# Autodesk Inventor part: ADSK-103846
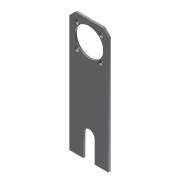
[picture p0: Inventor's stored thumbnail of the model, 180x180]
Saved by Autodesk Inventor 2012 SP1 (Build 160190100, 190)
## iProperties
Shininess: 20.0
Created: 2001-05
Part Number: ADSK-103846
Document SubType Name: Modeling
Designer: Administrator
Stock Number: ADSK-103846
Density: 1 g/cm^3
Material: Default
Density: 0.0
Volumn: 0.0
Area: 0.0
PropertySet Name: Model Information
Control State: 0
Master: False
Checked Out: False
Author: Administrator
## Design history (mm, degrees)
sketch "Sketch1"
  geometry: L1 (-24.57, 245.796)-(64.33, 245.796); L2 (64.33, 245.796)-(64.33, -33.604); L3 (64.33, -33.604)-(-24.57, -33.604); L4 (-24.57, -33.604)-(-24.57, 245.796)
  constraints: 8 end point, 2 parallel, 1 horizontal, 1 perpendicular
  dimensions: "d0" = 279.4 distance of L3.end L1.start; "d1" = 88.9 distance of L2.end L3.end
extrude "Extrusion1" new body sketch "Sketch1" distance "d2" = 4.7752; taper "d3" = 0 deg
sketch "Sketch2"
  geometry: L1 (-24.57, 245.796)-(64.33, 245.796) reference; L2 (-24.57, -33.604)-(-24.57, 245.796) reference; C1 r 32.385 at (19.88, 201.346)
  constraints: 1 centre point
  dimensions: "d4" = 64.77 diameter of C1; "d5" = 44.45 distance from line of L1 C1.centre; "d6" = 44.45 distance from line of L2 C1.centre (= d5)
extrude "Extrusion2" cut sketch "Sketch2" distance "d7" = 6.35; taper "d8" = 0 deg
sketch "Sketch3"
  geometry: L1 (64.33, 245.796)-(64.33, -33.604) reference; L2 (19.88, 201.346)-(46.821, 174.405); C1 r 32.385 at (19.88, 201.346) reference
  constraints: 2 end point
  dimensions: "d21" = 38.1 distance of L2.start L2.end; "d22" = 45 deg angle of L1 L2
hole "Hole1" sketch "Sketch3" at (46.821, 174.405) diameter "d9" = 5.55625; stored, may be unused: countersink angle "d13" = 82 deg, drill point angle "d15" = 118 deg; dims "d10" = 12.7, "d11" = 10.4775, "d12" = 6.35, "d14" = 19.05
pattern_circular "Circular Pattern1" dims angle "d18" = 360 deg
chamfer "Chamfer1" distance "d19" = 12.7; stored, may be unused: second distance "d20" = 12.7, angle "d29" = 45 deg
sketch "Sketch4"
  geometry: L1 (-24.57, -33.604)-(-24.57, 233.096) reference; L2 (64.33, -33.604)-(-24.57, -33.604) reference; L3 (64.33, 233.096)-(64.33, -33.604) reference; L4 (7.18, -33.604)-(32.58, -33.604); L5 (32.58, -33.604)-(32.58, 17.196); L6 (32.58, 17.196)-(7.18, 17.196); L7 (7.18, 17.196)-(7.18, -33.604); 1 further point
  constraints: 8 end point, 2 parallel, 1 horizontal, 1 horizontal alignment, 1 midpoint, 1 perpendicular, 1 point on line, 2 other
  dimensions: "d23" = 25.4 distance of L5.end L6.end; "d24" = 31.75 distance between parallel lines of L1 L7; "d25" = 31.75 distance between parallel lines of L3 L5 (derived); "d26" = 50.8 distance between parallel lines of L2 L6
extrude "Extrusion3" cut sketch "Sketch4" distance "d27" = 25.4; taper "d28" = 0 deg
workplane "Work Plane1"
body "Solid1"
